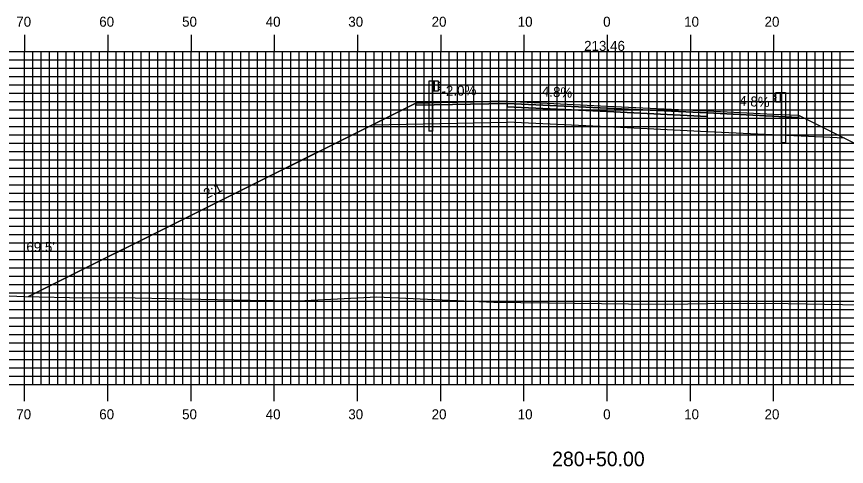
# Model space of a CAD drawing. Extents: x 1810980 to 1811323, y 442591 to 442811.
# Drawn here: x 1811074.9 to 1811174.6, y 442658.8 to 442712.9 of the extents above; entities that cross this region are included whole.
import ezdxf

# ---------------------------------------------------------------- set-up
doc = ezdxf.new("R2010")
doc.units = 0
for name, color, linetype in [('ANNOTATION', 7, 'Continuous'), ('D_Guardrail_Beam_Lt', 7, 'Continuous'), ('D_Guardrail_Beam_Rt', 7, 'Continuous'), ('D_Roadway_Centerline', 7, 'Continuous'), ('D_Roadway_Centerline_Text', 7, 'Continuous'), ('D_Roadway_Edge_Shoulder', 7, 'Continuous'), ('D_Roadway_Edge_TW', 7, 'Continuous'), ('D_Roadway_Pavement', 7, 'Continuous'), ('D_Roadway_SlopeLines', 7, 'Continuous'), ('D_Roadway_SubGrade', 7, 'Continuous'), ('D_Text_Standard', 7, 'Continuous'), ('H_V ANNOTATION', 7, 'Continuous'), ('MAJOR', 7, 'Continuous'), ('MINOR', 7, 'Continuous'), ('S_Roadway_Centerline', 7, 'Continuous')]:
    doc.layers.add(name, color=color, linetype=linetype)

msp = doc.modelspace()

# ---------------------------------------------------------------- linework, layer by layer
at = {"layer": 'D_Guardrail_Beam_Lt'}
for p, q in [((1811124.461, 442705.12), (1811124.461, 442699.12)), ((1811124.931, 442705.12), (1811124.461, 442705.12)), ((1811125.619, 442705.12), (1811124.931, 442705.12)), ((1811124.931, 442705.12), (1811124.931, 442703.953)), ((1811124.994, 442705.12), (1811124.994, 442703.953)), ((1811125.098, 442705.12), (1811125.098, 442703.953)), ((1811125.619, 442703.953), (1811125.619, 442705.12)), ((1811125.619, 442705.036), (1811125.693, 442705.022)), ((1811125.852, 442704.772), (1811125.657, 442704.636)), ((1811125.709, 442705.015), (1811125.852, 442704.915)), ((1811124.931, 442703.953), (1811125.619, 442703.953)), ((1811124.952, 442699.12), (1811124.952, 442703.953)), ((1811125.693, 442704.051), (1811125.619, 442704.036)), ((1811125.623, 442704.571), (1811125.623, 442704.501)), ((1811125.657, 442704.437), (1811125.852, 442704.301)), ((1811125.852, 442704.157), (1811125.709, 442704.057)), ((1811124.952, 442699.12), (1811124.461, 442699.12))]:
    msp.add_line(p, q, dxfattribs=at)
for centre, major_axis, start_param, end_param in [((1811125.685, 442704.981), (0.0417, 0), 0.959931, 1.376053), ((1811125.802, 442704.843), (0.0877, 0), 5.323254, 7.243116), ((1811125.702, 442704.571), (-0.0789, 0), 5.323254, 6.283185), ((1811125.702, 442704.501), (-0.0789, 0), 6.283185, 7.243116), ((1811125.685, 442704.091), (0.0417, 0), 4.907132, 5.323254), ((1811125.802, 442704.229), (0.0877, 0), 5.323254, 7.243116)]:
    msp.add_ellipse(centre, major_axis=major_axis, ratio=0.995501, start_param=start_param, end_param=end_param, dxfattribs=at)
at = {"layer": 'D_Guardrail_Beam_Rt'}
for p, q in [((1811166.161, 442703.744), (1811166.848, 442703.744)), ((1811166.161, 442702.577), (1811166.161, 442703.744)), ((1811166.681, 442703.744), (1811166.681, 442702.577)), ((1811166.786, 442703.744), (1811166.786, 442702.577)), ((1811166.848, 442703.744), (1811167.319, 442703.744)), ((1811166.848, 442703.744), (1811166.848, 442702.577)), ((1811167.319, 442703.744), (1811167.319, 442697.744)), ((1811166.071, 442703.639), (1811165.927, 442703.539)), ((1811165.927, 442703.396), (1811166.122, 442703.26)), ((1811166.122, 442703.061), (1811165.927, 442702.925)), ((1811165.927, 442702.781), (1811166.071, 442702.681)), ((1811166.161, 442703.66), (1811166.086, 442703.646)), ((1811166.156, 442703.195), (1811166.156, 442703.125)), ((1811166.086, 442702.675), (1811166.161, 442702.66)), ((1811166.848, 442702.577), (1811166.161, 442702.577)), ((1811166.827, 442697.744), (1811166.827, 442702.577)), ((1811166.827, 442697.744), (1811167.319, 442697.744))]:
    msp.add_line(p, q, dxfattribs=at)
for centre, major_axis, start_param, end_param in [((1811165.977, 442703.467), (-0.0877, 0), 5.323254, 7.243116), ((1811165.977, 442702.853), (-0.0877, 0), 5.323254, 7.243116), ((1811166.094, 442703.605), (-0.0417, 0), 4.907132, 5.323254), ((1811166.077, 442703.195), (0.0789, 0), 0, 0.959931), ((1811166.077, 442703.125), (0.0789, 0), 5.323254, 6.283185), ((1811166.094, 442702.715), (-0.0417, 0), 0.959931, 1.376053)]:
    msp.add_ellipse(centre, major_axis=major_axis, ratio=0.995501, start_param=start_param, end_param=end_param, dxfattribs=at)
at = {"layer": 'D_Roadway_Centerline'}
msp.add_lwpolyline([(1811076.356, 442679.209), (1811117.681, 442699.872), (1811122.89, 442702.476), (1811125.89, 442702.536), (1811133.89, 442702.696), (1811145.89, 442702.12), (1811157.89, 442701.544), (1811165.89, 442701.16), (1811168.89, 442701.016), (1811174.421, 442698.251), (1811215.155, 442677.884)], dxfattribs=at)
at = {"layer": 'D_Roadway_Edge_Shoulder'}
for points in [[(1811133.89, 442702.696), (1811125.89, 442702.536), (1811125.89, 442702.536), (1811122.89, 442702.476), (1811122.89, 442702.226), (1811133.89, 442702.446)], [(1811157.89, 442701.544), (1811165.89, 442701.16), (1811165.89, 442701.16), (1811168.89, 442701.016), (1811168.89, 442700.766), (1811157.89, 442701.294)]]:
    msp.add_lwpolyline(points, close=True, dxfattribs=at)
at = {"layer": 'D_Roadway_Edge_TW'}
msp.add_lwpolyline([(1811133.89, 442702.446), (1811133.89, 442702.696), (1811145.89, 442702.12), (1811157.89, 442701.544), (1811157.89, 442701.294), (1811145.89, 442701.87)], close=True, dxfattribs=at)
at = {"layer": 'D_Roadway_Pavement'}
msp.add_lwpolyline([(1811133.89, 442702.03), (1811133.89, 442702.446), (1811145.89, 442701.87), (1811157.89, 442701.294), (1811157.89, 442700.878), (1811145.89, 442701.454)], close=True, dxfattribs=at)
for points in [[(1811133.89, 442702.446), (1811133.89, 442702.03)], [(1811157.89, 442701.294), (1811157.89, 442700.878)]]:
    msp.add_lwpolyline(points, dxfattribs=at)
at = {"layer": 'D_Roadway_SlopeLines'}
for points in [[(1811122.89, 442702.476), (1811076.356, 442679.209)], [(1811168.89, 442701.016), (1811215.155, 442677.884)]]:
    msp.add_lwpolyline(points, dxfattribs=at)
at = {"layer": 'D_Roadway_SubGrade'}
for points in [[(1811133.89, 442702.03), (1811133.89, 442702.446), (1811122.89, 442702.226), (1811122.89, 442702.476), (1811117.681, 442699.872), (1811133.89, 442700.196)], [(1811133.89, 442700.196), (1811133.89, 442702.446), (1811133.89, 442702.03), (1811145.89, 442701.454), (1811157.89, 442700.878), (1811157.89, 442701.294), (1811157.89, 442699.044), (1811145.89, 442699.62)], [(1811157.89, 442700.878), (1811157.89, 442701.294), (1811168.89, 442700.766), (1811168.89, 442701.016), (1811174.421, 442698.251), (1811157.89, 442699.044)]]:
    msp.add_lwpolyline(points, close=True, dxfattribs=at)
at = {"layer": 'MAJOR'}
for p, q in [((1811075.89, 442710.669), (1811075.89, 442708.665)), ((1811085.89, 442710.669), (1811085.89, 442708.665)), ((1811095.89, 442710.669), (1811095.89, 442708.665)), ((1811105.89, 442710.669), (1811105.89, 442708.665)), ((1811115.89, 442710.669), (1811115.89, 442708.665)), ((1811125.89, 442710.669), (1811125.89, 442708.665)), ((1811135.89, 442710.669), (1811135.89, 442708.665)), ((1811145.89, 442710.669), (1811145.89, 442708.665)), ((1811155.89, 442710.669), (1811155.89, 442708.665)), ((1811165.89, 442710.669), (1811165.89, 442708.665)), ((1811005.89, 442708.665), (1811285.89, 442708.665)), ((1811005.89, 442708.665), (1811285.89, 442708.665)), ((1811075.89, 442668.665), (1811075.89, 442708.665)), ((1811085.89, 442668.665), (1811085.89, 442708.665)), ((1811095.89, 442668.665), (1811095.89, 442708.665)), ((1811105.89, 442668.665), (1811105.89, 442708.665)), ((1811115.89, 442668.665), (1811115.89, 442708.665)), ((1811125.89, 442668.665), (1811125.89, 442708.665)), ((1811135.89, 442668.665), (1811135.89, 442708.665)), ((1811145.89, 442668.665), (1811145.89, 442708.665)), ((1811155.89, 442668.665), (1811155.89, 442708.665)), ((1811165.89, 442668.665), (1811165.89, 442708.665)), ((1811005.89, 442703.665), (1811285.89, 442703.665)), ((1811005.89, 442698.665), (1811285.89, 442698.665)), ((1811005.89, 442693.665), (1811285.89, 442693.665)), ((1811005.89, 442688.665), (1811285.89, 442688.665)), ((1811005.89, 442683.665), (1811285.89, 442683.665)), ((1811005.89, 442678.665), (1811285.89, 442678.665)), ((1811005.89, 442673.665), (1811285.89, 442673.665)), ((1811005.89, 442668.665), (1811285.89, 442668.665)), ((1811005.89, 442668.665), (1811285.89, 442668.665)), ((1811075.89, 442666.661), (1811075.89, 442668.665)), ((1811085.89, 442666.661), (1811085.89, 442668.665)), ((1811095.89, 442666.661), (1811095.89, 442668.665)), ((1811105.89, 442666.661), (1811105.89, 442668.665)), ((1811115.89, 442666.661), (1811115.89, 442668.665)), ((1811125.89, 442666.661), (1811125.89, 442668.665)), ((1811135.89, 442666.661), (1811135.89, 442668.665)), ((1811145.89, 442666.661), (1811145.89, 442668.665)), ((1811155.89, 442666.661), (1811155.89, 442668.665)), ((1811165.89, 442666.661), (1811165.89, 442668.665))]:
    msp.add_line(p, q, dxfattribs=at)
at = {"layer": 'MINOR'}
for p, q in [((1811076.89, 442668.665), (1811076.89, 442708.665)), ((1811077.89, 442668.665), (1811077.89, 442708.665)), ((1811078.89, 442668.665), (1811078.89, 442708.665)), ((1811079.89, 442668.665), (1811079.89, 442708.665)), ((1811080.89, 442668.665), (1811080.89, 442708.665)), ((1811081.89, 442668.665), (1811081.89, 442708.665)), ((1811082.89, 442668.665), (1811082.89, 442708.665)), ((1811083.89, 442668.665), (1811083.89, 442708.665)), ((1811084.89, 442668.665), (1811084.89, 442708.665)), ((1811086.89, 442668.665), (1811086.89, 442708.665)), ((1811087.89, 442668.665), (1811087.89, 442708.665)), ((1811088.89, 442668.665), (1811088.89, 442708.665)), ((1811089.89, 442668.665), (1811089.89, 442708.665)), ((1811090.89, 442668.665), (1811090.89, 442708.665)), ((1811091.89, 442668.665), (1811091.89, 442708.665)), ((1811092.89, 442668.665), (1811092.89, 442708.665)), ((1811093.89, 442668.665), (1811093.89, 442708.665)), ((1811094.89, 442668.665), (1811094.89, 442708.665)), ((1811096.89, 442668.665), (1811096.89, 442708.665)), ((1811097.89, 442668.665), (1811097.89, 442708.665)), ((1811098.89, 442668.665), (1811098.89, 442708.665)), ((1811099.89, 442668.665), (1811099.89, 442708.665)), ((1811100.89, 442668.665), (1811100.89, 442708.665)), ((1811101.89, 442668.665), (1811101.89, 442708.665)), ((1811102.89, 442668.665), (1811102.89, 442708.665)), ((1811103.89, 442668.665), (1811103.89, 442708.665)), ((1811104.89, 442668.665), (1811104.89, 442708.665)), ((1811106.89, 442668.665), (1811106.89, 442708.665)), ((1811107.89, 442668.665), (1811107.89, 442708.665)), ((1811108.89, 442668.665), (1811108.89, 442708.665)), ((1811109.89, 442668.665), (1811109.89, 442708.665)), ((1811110.89, 442668.665), (1811110.89, 442708.665)), ((1811111.89, 442668.665), (1811111.89, 442708.665)), ((1811112.89, 442668.665), (1811112.89, 442708.665)), ((1811113.89, 442668.665), (1811113.89, 442708.665)), ((1811114.89, 442668.665), (1811114.89, 442708.665)), ((1811116.89, 442668.665), (1811116.89, 442708.665)), ((1811117.89, 442668.665), (1811117.89, 442708.665)), ((1811118.89, 442668.665), (1811118.89, 442708.665)), ((1811119.89, 442668.665), (1811119.89, 442708.665)), ((1811120.89, 442668.665), (1811120.89, 442708.665)), ((1811121.89, 442668.665), (1811121.89, 442708.665)), ((1811122.89, 442668.665), (1811122.89, 442708.665)), ((1811123.89, 442668.665), (1811123.89, 442708.665)), ((1811124.89, 442668.665), (1811124.89, 442708.665)), ((1811126.89, 442668.665), (1811126.89, 442708.665)), ((1811127.89, 442668.665), (1811127.89, 442708.665)), ((1811128.89, 442668.665), (1811128.89, 442708.665)), ((1811129.89, 442668.665), (1811129.89, 442708.665)), ((1811130.89, 442668.665), (1811130.89, 442708.665)), ((1811131.89, 442668.665), (1811131.89, 442708.665)), ((1811132.89, 442668.665), (1811132.89, 442708.665)), ((1811133.89, 442668.665), (1811133.89, 442708.665)), ((1811134.89, 442668.665), (1811134.89, 442708.665)), ((1811136.89, 442668.665), (1811136.89, 442708.665)), ((1811137.89, 442668.665), (1811137.89, 442708.665)), ((1811138.89, 442668.665), (1811138.89, 442708.665)), ((1811139.89, 442668.665), (1811139.89, 442708.665)), ((1811140.89, 442668.665), (1811140.89, 442708.665)), ((1811141.89, 442668.665), (1811141.89, 442708.665)), ((1811142.89, 442668.665), (1811142.89, 442708.665)), ((1811143.89, 442668.665), (1811143.89, 442708.665)), ((1811144.89, 442668.665), (1811144.89, 442708.665)), ((1811146.89, 442668.665), (1811146.89, 442708.665)), ((1811147.89, 442668.665), (1811147.89, 442708.665)), ((1811148.89, 442668.665), (1811148.89, 442708.665)), ((1811149.89, 442668.665), (1811149.89, 442708.665)), ((1811150.89, 442668.665), (1811150.89, 442708.665)), ((1811151.89, 442668.665), (1811151.89, 442708.665)), ((1811152.89, 442668.665), (1811152.89, 442708.665)), ((1811153.89, 442668.665), (1811153.89, 442708.665)), ((1811154.89, 442668.665), (1811154.89, 442708.665)), ((1811156.89, 442668.665), (1811156.89, 442708.665)), ((1811157.89, 442668.665), (1811157.89, 442708.665)), ((1811158.89, 442668.665), (1811158.89, 442708.665)), ((1811159.89, 442668.665), (1811159.89, 442708.665)), ((1811160.89, 442668.665), (1811160.89, 442708.665)), ((1811161.89, 442668.665), (1811161.89, 442708.665)), ((1811162.89, 442668.665), (1811162.89, 442708.665)), ((1811163.89, 442668.665), (1811163.89, 442708.665)), ((1811164.89, 442668.665), (1811164.89, 442708.665)), ((1811166.89, 442668.665), (1811166.89, 442708.665)), ((1811167.89, 442668.665), (1811167.89, 442708.665)), ((1811168.89, 442668.665), (1811168.89, 442708.665)), ((1811169.89, 442668.665), (1811169.89, 442708.665)), ((1811170.89, 442668.665), (1811170.89, 442708.665)), ((1811171.89, 442668.665), (1811171.89, 442708.665)), ((1811172.89, 442668.665), (1811172.89, 442708.665)), ((1811173.89, 442668.665), (1811173.89, 442708.665)), ((1811005.89, 442707.665), (1811285.89, 442707.665)), ((1811005.89, 442706.665), (1811285.89, 442706.665)), ((1811005.89, 442705.665), (1811285.89, 442705.665)), ((1811005.89, 442704.665), (1811285.89, 442704.665)), ((1811005.89, 442702.665), (1811285.89, 442702.665)), ((1811005.89, 442701.665), (1811285.89, 442701.665)), ((1811005.89, 442700.665), (1811285.89, 442700.665)), ((1811005.89, 442699.665), (1811285.89, 442699.665)), ((1811005.89, 442697.665), (1811285.89, 442697.665)), ((1811005.89, 442696.665), (1811285.89, 442696.665)), ((1811005.89, 442695.665), (1811285.89, 442695.665)), ((1811005.89, 442694.665), (1811285.89, 442694.665)), ((1811005.89, 442692.665), (1811285.89, 442692.665)), ((1811005.89, 442691.665), (1811285.89, 442691.665)), ((1811005.89, 442690.665), (1811285.89, 442690.665)), ((1811005.89, 442689.665), (1811285.89, 442689.665)), ((1811005.89, 442687.665), (1811285.89, 442687.665)), ((1811005.89, 442686.665), (1811285.89, 442686.665)), ((1811005.89, 442685.665), (1811285.89, 442685.665)), ((1811005.89, 442684.665), (1811285.89, 442684.665)), ((1811005.89, 442682.665), (1811285.89, 442682.665)), ((1811005.89, 442681.665), (1811285.89, 442681.665)), ((1811005.89, 442680.665), (1811285.89, 442680.665)), ((1811005.89, 442679.665), (1811285.89, 442679.665)), ((1811005.89, 442677.665), (1811285.89, 442677.665)), ((1811005.89, 442676.665), (1811285.89, 442676.665)), ((1811005.89, 442675.665), (1811285.89, 442675.665)), ((1811005.89, 442674.665), (1811285.89, 442674.665)), ((1811005.89, 442672.665), (1811285.89, 442672.665)), ((1811005.89, 442671.665), (1811285.89, 442671.665)), ((1811005.89, 442670.665), (1811285.89, 442670.665)), ((1811005.89, 442669.665), (1811285.89, 442669.665))]:
    msp.add_line(p, q, dxfattribs=at)
at = {"layer": 'S_Roadway_Centerline'}
msp.add_lwpolyline([(1811005.89, 442681.016), (1811008.301, 442680.997), (1811011.856, 442680.83), (1811016.783, 442680.656), (1811023.863, 442680.433), (1811028.723, 442680.329), (1811046.373, 442679.868), (1811047.914, 442679.852), (1811051.498, 442679.743), (1811067.226, 442679.493), (1811070.431, 442679.474), (1811075.853, 442679.221), (1811083.077, 442679.056), (1811087.208, 442679.092), (1811102.999, 442678.789), (1811108.778, 442678.687), (1811118.225, 442679.17), (1811127.785, 442678.763), (1811132.283, 442678.563), (1811148.458, 442678.361), (1811153.14, 442678.309), (1811160.432, 442678.413), (1811167.63, 442678.398), (1811180.709, 442678.135)], dxfattribs=at)

# ---------------------------------------------------------------- texts
at = {"layer": 'ANNOTATION'}
for s, rotation, p in [('-2.0%', 1.14576, (1811125.996, 442703.339)), ('4.8%', 357.25191, (1811138.019, 442703.3)), ('-4.8%', 357.25191, (1811161.198, 442702.188)), ('2:1', 26.56505, (1811097.768, 442690.952))]:
    msp.add_text(s, height=1.2, rotation=rotation, dxfattribs=at).set_placement(p)
at = {"layer": 'D_Roadway_Centerline'}
for s, p in [('C', (1811145.884, 442702.12)), ('L', (1811145.89, 442702.113))]:
    msp.add_text(s, height=0.0146, dxfattribs=at).set_placement(p)
at = {"layer": 'D_Roadway_Centerline_Text'}
msp.add_text('213.46', height=1.2, dxfattribs=at).set_placement((1811143.118, 442708.759))
at = {"layer": 'D_Text_Standard'}
msp.add_text("69.5'", height=1.2, dxfattribs=at).set_placement((1811076.11, 442684.586))
at = {"layer": 'H_V ANNOTATION'}
for s, height, p in [('70', 1.2, (1811074.894, 442711.665)), ('60', 1.2, (1811084.862, 442711.665)), ('50', 1.2, (1811094.819, 442711.665)), ('40', 1.2, (1811104.862, 442711.665)), ('30', 1.2, (1811114.787, 442711.665)), ('20', 1.2, (1811124.798, 442711.665)), ('10', 1.2, (1811135.14, 442711.665)), ('0', 1.2, (1811145.408, 442711.665)), ('10', 1.2, (1811155.14, 442711.665)), ('20', 1.2, (1811164.798, 442711.665)), ('70', 1.2, (1811074.894, 442664.465)), ('60', 1.2, (1811084.862, 442664.465)), ('50', 1.2, (1811094.819, 442664.465)), ('40', 1.2, (1811104.862, 442664.465)), ('30', 1.2, (1811114.787, 442664.465)), ('20', 1.2, (1811124.798, 442664.465)), ('10', 1.2, (1811135.14, 442664.465)), ('0', 1.2, (1811145.408, 442664.465)), ('10', 1.2, (1811155.14, 442664.465)), ('20', 1.2, (1811164.798, 442664.465)), ('280+50.00', 1.75, (1811139.272, 442658.821))]:
    msp.add_text(s, height=height, dxfattribs=at).set_placement(p)

doc.saveas('drawing.dxf')
